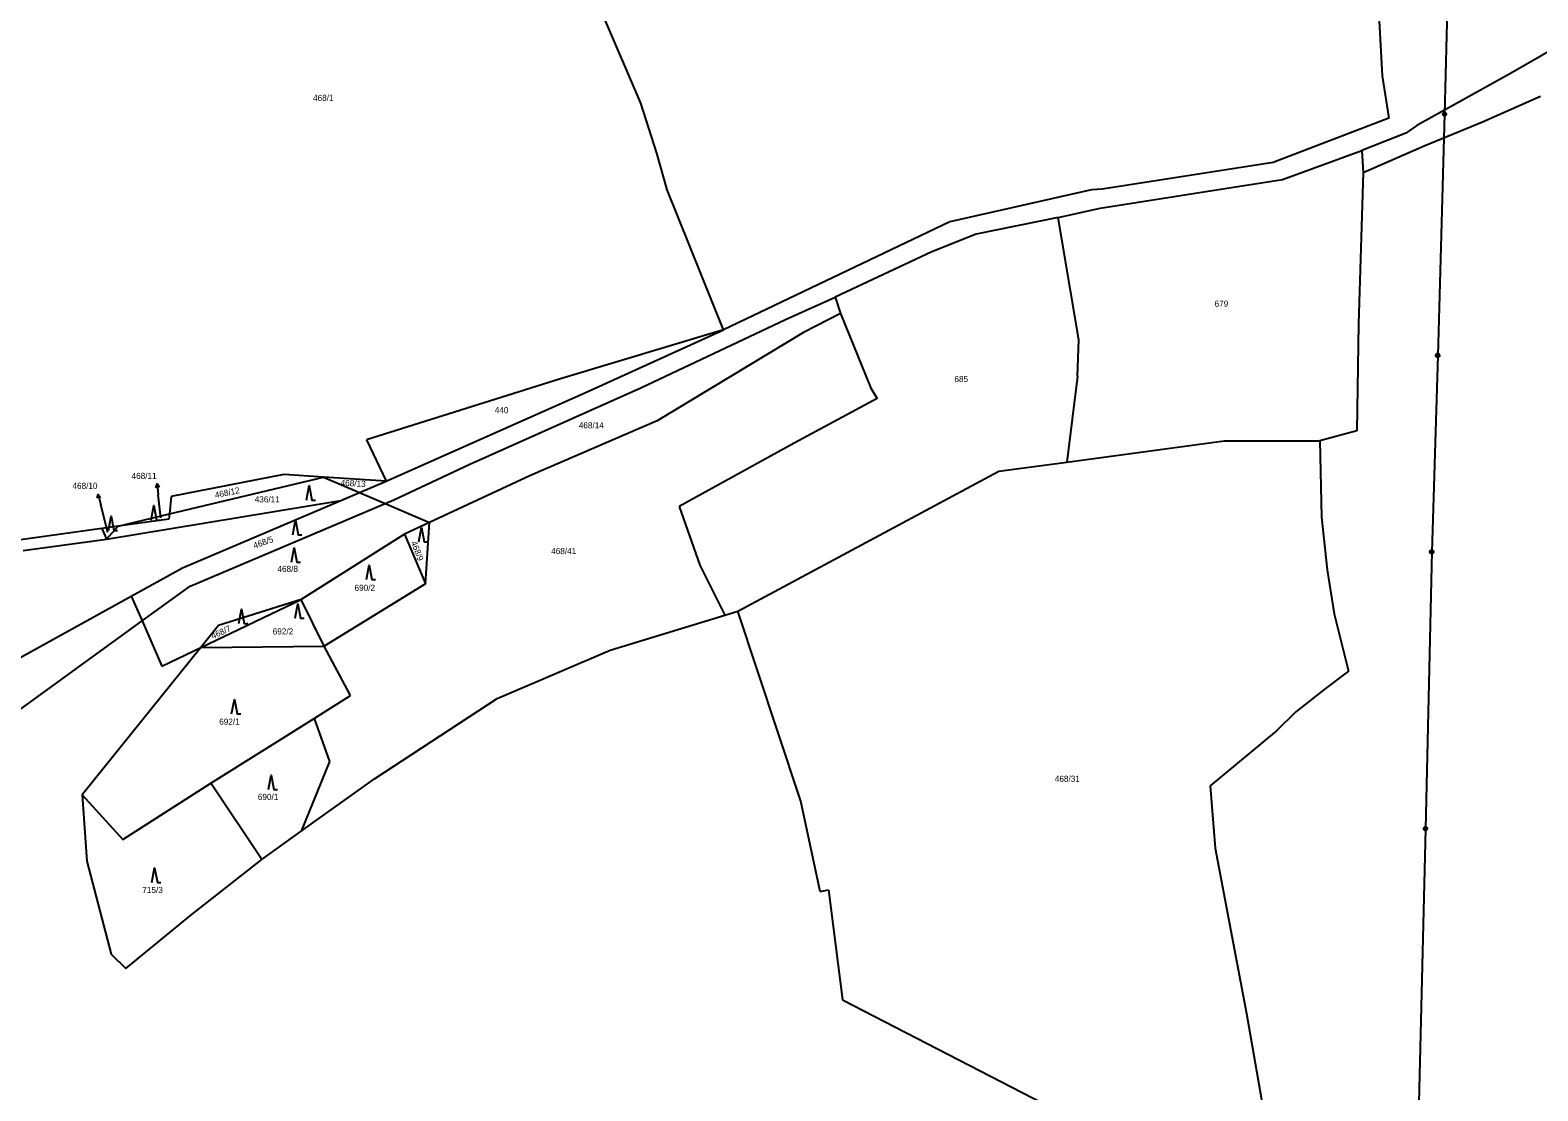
# Model space of a CAD drawing. Extents: x -852001 to -842497, y -1063614 to -1052182.
# Drawn here: x -845490.2 to -845072.7, y -1062182 to -1061888.4 of the extents above; entities that cross this region are included whole.
import ezdxf

# ---------------------------------------------------------------- set-up
doc = ezdxf.new("R2010")
doc.units = 0
for name, color, linetype in [('Default', 7, 'Continuous'), ('KN_HRANICE', 7, 'Continuous'), ('KN_KULTURY', 7, 'Continuous'), ('KN_PARCELY', 7, 'Continuous'), ('KN_VEDENI', 7, 'Continuous')]:
    doc.layers.add(name, color=color, linetype=linetype)

# ---------------------------------------------------------------- blocks, each defined once
blk = doc.blocks.new('308')
at = {"layer": 'Default'}
blk.add_lwpolyline([(-0.75, 0), (0, 4), (0.75, 0), (1.75, 0)], dxfattribs=at)
blk = doc.blocks.new('10292')
at = {"layer": 'Default'}
blk.add_line((0, 3), (0, 0), dxfattribs=at)
blk.add_lwpolyline([(-0.5, 2), (0, 3), (0.5, 2)], dxfattribs=at)
blk = doc.blocks.new('601')
at = {"layer": 'Default'}
blk.add_lwpolyline([(-0.15, 0.48), (0.16, 0.48), (0.41, 0.3), (0.51, 0.01), (0.41, -0.28), (0.16, -0.46), (-0.15, -0.46), (-0.4, -0.28), (-0.5, 0.01), (-0.4, 0.3), (-0.15, 0.48), (-0.12, 0.44), (0.12, 0.44), (0.28, 0.36), (-0.28, 0.36), (-0.36, 0.28), (0.36, 0.28), (0.36, 0.2), (-0.36, 0.2), (-0.4, 0.12), (0.4, 0.12), (0.44, 0.04), (-0.44, 0.04), (-0.44, -0.04), (0.44, -0.04), (0.41, -0.12), (-0.4, -0.12), (-0.39, -0.2), (0.42, -0.2), (0.37, -0.28), (-0.35, -0.28), (-0.27, -0.36), (0.29, -0.36), (0.18, -0.44), (-0.16, -0.44)], dxfattribs=at)

msp = doc.modelspace()

# ---------------------------------------------------------------- linework, layer by layer
at = {"layer": 'KN_HRANICE'}
for p, q in [((-845117.56, -1061869.75), (-845115.87, -1061901.09)), ((-845117.56, -1061869.75), (-845115.87, -1061901.09)), ((-845321.09, -1061908.67), (-845331.76, -1061883.94)), ((-845321.09, -1061908.67), (-845331.76, -1061883.94)), ((-845067.31, -1061892.92), (-845080.32, -1061900.42)), ((-845067.31, -1061892.92), (-845080.32, -1061900.42)), ((-845115.87, -1061901.09), (-845114, -1061912.83)), ((-845115.87, -1061901.09), (-845114, -1061912.83)), ((-845080.32, -1061900.42), (-845094.38, -1061908.29)), ((-845080.32, -1061900.42), (-845094.38, -1061908.29)), ((-845094.38, -1061908.29), (-845106.22, -1061914.77)), ((-845094.38, -1061908.29), (-845106.22, -1061914.77)), ((-845088.09, -1061913.84), (-845071.99, -1061906.71)), ((-845088.09, -1061913.84), (-845071.99, -1061906.71)), ((-845316.7, -1061922.48), (-845321.09, -1061908.67)), ((-845316.7, -1061922.48), (-845321.09, -1061908.67)), ((-845114, -1061912.83), (-845146, -1061925.02)), ((-845114, -1061912.83), (-845146, -1061925.02)), ((-845109.28, -1061916.9), (-845121.49, -1061921.71)), ((-845109.28, -1061916.9), (-845121.49, -1061921.71)), ((-845106.22, -1061914.77), (-845109.28, -1061916.9)), ((-845106.22, -1061914.77), (-845109.28, -1061916.9)), ((-845104.19, -1061920.41), (-845088.09, -1061913.84)), ((-845104.19, -1061920.41), (-845088.09, -1061913.84)), ((-845121.12, -1061927.82), (-845104.19, -1061920.41)), ((-845121.12, -1061927.82), (-845104.19, -1061920.41)), ((-845313.82, -1061932.65), (-845316.7, -1061922.48)), ((-845313.82, -1061932.65), (-845316.7, -1061922.48)), ((-845146, -1061925.02), (-845193.41, -1061932.48)), ((-845146, -1061925.02), (-845193.41, -1061932.48)), ((-845143.47, -1061929.78), (-845121.49, -1061921.71)), ((-845143.47, -1061929.78), (-845121.49, -1061921.71)), ((-845121.49, -1061921.71), (-845121.12, -1061927.82)), ((-845121.49, -1061921.71), (-845121.12, -1061927.82)), ((-845121.12, -1061927.82), (-845122.4, -1061969.73)), ((-845121.12, -1061927.82), (-845122.4, -1061969.73)), ((-845298.2, -1061971.35), (-845313.82, -1061932.65)), ((-845298.2, -1061971.35), (-845313.82, -1061932.65)), ((-845196.29, -1061932.65), (-845235.53, -1061941.44)), ((-845196.29, -1061932.65), (-845235.53, -1061941.44)), ((-845193.41, -1061932.48), (-845196.29, -1061932.65)), ((-845193.41, -1061932.48), (-845196.29, -1061932.65)), ((-845193.91, -1061937.74), (-845164.67, -1061933.11)), ((-845193.91, -1061937.74), (-845164.67, -1061933.11)), ((-845164.67, -1061933.11), (-845143.47, -1061929.78)), ((-845164.67, -1061933.11), (-845143.47, -1061929.78)), ((-845205.52, -1061940.3), (-845193.91, -1061937.74)), ((-845205.52, -1061940.3), (-845193.91, -1061937.74)), ((-845235.53, -1061941.44), (-845298.2, -1061971.35)), ((-845235.53, -1061941.44), (-845298.2, -1061971.35)), ((-845205.52, -1061940.3), (-845228.28, -1061944.89)), ((-845205.52, -1061940.3), (-845228.28, -1061944.89)), ((-845199.81, -1061974.13), (-845205.52, -1061940.3)), ((-845199.81, -1061974.13), (-845205.52, -1061940.3)), ((-845228.28, -1061944.89), (-845240.56, -1061949.77)), ((-845228.28, -1061944.89), (-845240.56, -1061949.77)), ((-845240.56, -1061949.77), (-845267.32, -1061962.35)), ((-845240.56, -1061949.77), (-845267.32, -1061962.35)), ((-845281.07, -1061968.54), (-845267.32, -1061962.35)), ((-845281.07, -1061968.54), (-845267.32, -1061962.35)), ((-845267.32, -1061962.35), (-845265.84, -1061966.86)), ((-845267.32, -1061962.35), (-845265.84, -1061966.86)), ((-845265.84, -1061966.86), (-845276.07, -1061972.09)), ((-845265.84, -1061966.86), (-845276.07, -1061972.09)), ((-845265.84, -1061966.86), (-845257.43, -1061987.52)), ((-845265.84, -1061966.86), (-845257.43, -1061987.52)), ((-845320.93, -1061987.31), (-845281.07, -1061968.54)), ((-845320.93, -1061987.31), (-845281.07, -1061968.54)), ((-845122.4, -1061969.73), (-845122.89, -1061999.33)), ((-845122.4, -1061969.73), (-845122.89, -1061999.33)), ((-845298.2, -1061971.35), (-845343.34, -1061984.91)), ((-845298.2, -1061971.35), (-845343.34, -1061984.91)), ((-845335.79, -1061988.4), (-845298.2, -1061971.35)), ((-845335.79, -1061988.4), (-845298.2, -1061971.35)), ((-845276.07, -1061972.09), (-845316.61, -1061996.53)), ((-845276.07, -1061972.09), (-845316.61, -1061996.53)), ((-845200.21, -1061984.17), (-845199.81, -1061974.13)), ((-845200.21, -1061984.17), (-845199.81, -1061974.13)), ((-845343.34, -1061984.91), (-845397.14, -1062001.82)), ((-845343.34, -1061984.91), (-845397.14, -1062001.82)), ((-845368.48, -1062008.59), (-845320.93, -1061987.31)), ((-845368.48, -1062008.59), (-845320.93, -1061987.31)), ((-845257.43, -1061987.52), (-845255.66, -1061990.37)), ((-845257.43, -1061987.52), (-845255.66, -1061990.37)), ((-845200.21, -1061984.17), (-845203.14, -1062007.97)), ((-845200.21, -1061984.17), (-845203.14, -1062007.97)), ((-845391.63, -1062013.24), (-845335.79, -1061988.4)), ((-845391.63, -1062013.24), (-845335.79, -1061988.4)), ((-845255.66, -1061990.37), (-845278.69, -1062002.78)), ((-845255.66, -1061990.37), (-845278.69, -1062002.78)), ((-845316.61, -1061996.53), (-845351.72, -1062011.72)), ((-845316.61, -1061996.53), (-845351.72, -1062011.72)), ((-845122.89, -1061999.33), (-845133.12, -1062002.1)), ((-845122.89, -1061999.33), (-845133.12, -1062002.1)), ((-845397.14, -1062001.82), (-845391.63, -1062013.24)), ((-845397.14, -1062001.82), (-845391.63, -1062013.24)), ((-845278.69, -1062002.78), (-845310.49, -1062020.31)), ((-845278.69, -1062002.78), (-845310.49, -1062020.31)), ((-845203.14, -1062007.97), (-845159.56, -1062002.1)), ((-845203.14, -1062007.97), (-845159.56, -1062002.1)), ((-845159.56, -1062002.1), (-845133.12, -1062002.1)), ((-845159.56, -1062002.1), (-845133.12, -1062002.1)), ((-845133.12, -1062002.1), (-845132.63, -1062023.19)), ((-845133.12, -1062002.1), (-845132.63, -1062023.19)), ((-845389.56, -1062018.44), (-845368.48, -1062008.59)), ((-845389.56, -1062018.44), (-845368.48, -1062008.59)), ((-845222, -1062010.51), (-845203.14, -1062007.97)), ((-845222, -1062010.51), (-845203.14, -1062007.97)), ((-845451.7, -1062022.34), (-845409.01, -1062012.14)), ((-845451.7, -1062022.34), (-845409.01, -1062012.14)), ((-845420, -1062011.44), (-845451.16, -1062017.46)), ((-845420, -1062011.44), (-845451.16, -1062017.46)), ((-845409.01, -1062012.14), (-845420, -1062011.44)), ((-845409.01, -1062012.14), (-845420, -1062011.44)), ((-845391.63, -1062013.24), (-845409.01, -1062012.14)), ((-845409.01, -1062012.14), (-845399.06, -1062016.4)), ((-845391.63, -1062013.24), (-845409.01, -1062012.14)), ((-845409.01, -1062012.14), (-845399.06, -1062016.4)), ((-845351.72, -1062011.72), (-845379.63, -1062024.73)), ((-845351.72, -1062011.72), (-845379.63, -1062024.73)), ((-845294.32, -1062049.22), (-845222, -1062010.51)), ((-845294.32, -1062049.22), (-845222, -1062010.51)), ((-845404.21, -1062018.6), (-845399.06, -1062016.4)), ((-845404.21, -1062018.6), (-845399.06, -1062016.4)), ((-845399.06, -1062016.4), (-845391.63, -1062013.24)), ((-845399.06, -1062016.4), (-845391.63, -1062013.24)), ((-845399.06, -1062016.4), (-845391.95, -1062019.45)), ((-845399.06, -1062016.4), (-845391.95, -1062019.45)), ((-845469.1, -1062029.34), (-845404.21, -1062018.6)), ((-845469.1, -1062029.34), (-845404.21, -1062018.6)), ((-845451.16, -1062017.46), (-845451.7, -1062022.34)), ((-845451.16, -1062017.46), (-845451.7, -1062022.34)), ((-845448.04, -1062037.26), (-845404.21, -1062018.6)), ((-845448.04, -1062037.26), (-845404.21, -1062018.6)), ((-845445.96, -1062042.32), (-845391.95, -1062019.45)), ((-845445.96, -1062042.32), (-845391.95, -1062019.45)), ((-845391.95, -1062019.45), (-845389.56, -1062018.44)), ((-845391.95, -1062019.45), (-845389.56, -1062018.44)), ((-845391.95, -1062019.45), (-845379.63, -1062024.73)), ((-845391.95, -1062019.45), (-845379.63, -1062024.73)), ((-845310.49, -1062020.31), (-845304.77, -1062036.51)), ((-845310.49, -1062020.31), (-845304.77, -1062036.51)), ((-845465.87, -1062025.72), (-845451.7, -1062022.34)), ((-845465.87, -1062025.72), (-845451.7, -1062022.34)), ((-845451.86, -1062023.75), (-845465.87, -1062025.72)), ((-845451.86, -1062023.75), (-845465.87, -1062025.72)), ((-845451.7, -1062022.34), (-845451.86, -1062023.75)), ((-845451.7, -1062022.34), (-845451.86, -1062023.75)), ((-845379.63, -1062024.73), (-845386.57, -1062027.96)), ((-845379.63, -1062024.73), (-845386.57, -1062027.96)), ((-845380.78, -1062041.68), (-845379.63, -1062024.73)), ((-845380.78, -1062041.68), (-845379.63, -1062024.73)), ((-845132.63, -1062023.19), (-845131.05, -1062037.82)), ((-845132.63, -1062023.19), (-845131.05, -1062037.82)), ((-845470.38, -1062026.35), (-845497.51, -1062030.16)), ((-845470.38, -1062026.35), (-845497.51, -1062030.16)), ((-845492.16, -1062032.41), (-845469.1, -1062029.34)), ((-845492.16, -1062032.41), (-845469.1, -1062029.34)), ((-845465.87, -1062025.72), (-845470.38, -1062026.35)), ((-845465.87, -1062025.72), (-845470.38, -1062026.35)), ((-845470.38, -1062026.35), (-845469.1, -1062029.34)), ((-845470.38, -1062026.35), (-845469.1, -1062029.34)), ((-845469.1, -1062029.34), (-845465.87, -1062025.72)), ((-845469.1, -1062029.34), (-845465.87, -1062025.72)), ((-845386.57, -1062027.96), (-845415.24, -1062046.05)), ((-845386.57, -1062027.96), (-845415.24, -1062046.05)), ((-845386.57, -1062027.96), (-845380.78, -1062041.68)), ((-845386.57, -1062027.96), (-845380.78, -1062041.68)), ((-845462.24, -1062045.1), (-845448.04, -1062037.26)), ((-845462.24, -1062045.1), (-845448.04, -1062037.26)), ((-845304.77, -1062036.51), (-845297.89, -1062050.36)), ((-845304.77, -1062036.51), (-845297.89, -1062050.36)), ((-845131.05, -1062037.82), (-845129.1, -1062050.01)), ((-845131.05, -1062037.82), (-845129.1, -1062050.01)), ((-845380.78, -1062041.68), (-845408.8, -1062058.9)), ((-845380.78, -1062041.68), (-845408.8, -1062058.9)), ((-845506.65, -1062069.62), (-845462.24, -1062045.1)), ((-845506.65, -1062069.62), (-845462.24, -1062045.1)), ((-845462.24, -1062045.1), (-845459.27, -1062051.94)), ((-845462.24, -1062045.1), (-845459.27, -1062051.94)), ((-845459.27, -1062051.94), (-845445.96, -1062042.32)), ((-845459.27, -1062051.94), (-845445.96, -1062042.32)), ((-845442.94, -1062059.27), (-845415.24, -1062046.05)), ((-845442.94, -1062059.27), (-845415.24, -1062046.05)), ((-845415.24, -1062046.05), (-845438.09, -1062053.25)), ((-845415.24, -1062046.05), (-845438.09, -1062053.25)), ((-845408.8, -1062058.9), (-845415.24, -1062046.05)), ((-845408.8, -1062058.9), (-845415.24, -1062046.05)), ((-845329.66, -1062060.07), (-845297.89, -1062050.36)), ((-845329.66, -1062060.07), (-845297.89, -1062050.36)), ((-845297.89, -1062050.36), (-845294.32, -1062049.22)), ((-845297.89, -1062050.36), (-845294.32, -1062049.22)), ((-845283.35, -1062082.09), (-845294.32, -1062049.22)), ((-845283.35, -1062082.09), (-845294.32, -1062049.22)), ((-845129.1, -1062050.01), (-845125.21, -1062065.8)), ((-845129.1, -1062050.01), (-845125.21, -1062065.8)), ((-845499.15, -1062080.77), (-845459.27, -1062051.94)), ((-845499.15, -1062080.77), (-845459.27, -1062051.94)), ((-845459.27, -1062051.94), (-845453.82, -1062064.46)), ((-845459.27, -1062051.94), (-845453.82, -1062064.46)), ((-845438.09, -1062053.25), (-845442.94, -1062059.27)), ((-845438.09, -1062053.25), (-845442.94, -1062059.27)), ((-845442.94, -1062059.27), (-845408.8, -1062058.9)), ((-845442.94, -1062059.27), (-845408.8, -1062058.9)), ((-845401.5, -1062072.6), (-845408.8, -1062058.9)), ((-845401.5, -1062072.6), (-845408.8, -1062058.9)), ((-845442.94, -1062059.27), (-845475.81, -1062100.03)), ((-845442.94, -1062059.27), (-845475.81, -1062100.03)), ((-845453.82, -1062064.46), (-845442.94, -1062059.27)), ((-845453.82, -1062064.46), (-845442.94, -1062059.27)), ((-845360.89, -1062073.42), (-845329.66, -1062060.07)), ((-845360.89, -1062073.42), (-845329.66, -1062060.07)), ((-845125.21, -1062065.8), (-845131.55, -1062070.67)), ((-845125.21, -1062065.8), (-845131.55, -1062070.67)), ((-845131.55, -1062070.67), (-845139.71, -1062077.13)), ((-845131.55, -1062070.67), (-845139.71, -1062077.13)), ((-845411.64, -1062078.95), (-845401.5, -1062072.6)), ((-845411.64, -1062078.95), (-845401.5, -1062072.6)), ((-845394.88, -1062095.61), (-845360.89, -1062073.42)), ((-845394.88, -1062095.61), (-845360.89, -1062073.42)), ((-845440.2, -1062096.85), (-845411.64, -1062078.95)), ((-845440.2, -1062096.85), (-845411.64, -1062078.95)), ((-845411.64, -1062078.95), (-845407.31, -1062090.85)), ((-845411.64, -1062078.95), (-845407.31, -1062090.85)), ((-845139.71, -1062077.13), (-845145.07, -1062082.37)), ((-845139.71, -1062077.13), (-845145.07, -1062082.37)), ((-845276.87, -1062101.86), (-845283.35, -1062082.09)), ((-845276.87, -1062101.86), (-845283.35, -1062082.09)), ((-845145.07, -1062082.37), (-845163.47, -1062097.61)), ((-845145.07, -1062082.37), (-845163.47, -1062097.61)), ((-845407.31, -1062090.85), (-845415.19, -1062110.13)), ((-845407.31, -1062090.85), (-845415.19, -1062110.13)), ((-845415.19, -1062110.13), (-845394.88, -1062095.61)), ((-845415.19, -1062110.13), (-845394.88, -1062095.61)), ((-845475.81, -1062100.03), (-845474.56, -1062118.39)), ((-845475.81, -1062100.03), (-845464.57, -1062112.48)), ((-845475.81, -1062100.03), (-845474.56, -1062118.39)), ((-845475.81, -1062100.03), (-845464.57, -1062112.48)), ((-845464.57, -1062112.48), (-845440.2, -1062096.85)), ((-845464.57, -1062112.48), (-845440.2, -1062096.85)), ((-845426.1, -1062117.93), (-845440.2, -1062096.85)), ((-845426.1, -1062117.93), (-845440.2, -1062096.85)), ((-845163.47, -1062097.61), (-845162.13, -1062114.85)), ((-845163.47, -1062097.61), (-845162.13, -1062114.85)), ((-845271.43, -1062126.82), (-845276.87, -1062101.86)), ((-845271.43, -1062126.82), (-845276.87, -1062101.86)), ((-845426.1, -1062117.93), (-845415.19, -1062110.13)), ((-845426.1, -1062117.93), (-845415.19, -1062110.13)), ((-845162.13, -1062114.85), (-845153.37, -1062160.62)), ((-845162.13, -1062114.85), (-845153.37, -1062160.62)), ((-845474.56, -1062118.39), (-845467.8, -1062144.19)), ((-845474.56, -1062118.39), (-845467.8, -1062144.19)), ((-845445.82, -1062133.47), (-845426.1, -1062117.93)), ((-845445.82, -1062133.47), (-845426.1, -1062117.93)), ((-845271.43, -1062126.82), (-845269.15, -1062126.37)), ((-845271.43, -1062126.82), (-845269.15, -1062126.37)), ((-845269.15, -1062126.37), (-845265.26, -1062156.82)), ((-845269.15, -1062126.37), (-845265.26, -1062156.82)), ((-845463.75, -1062148.16), (-845445.82, -1062133.47)), ((-845463.75, -1062148.16), (-845445.82, -1062133.47)), ((-845467.8, -1062144.19), (-845463.75, -1062148.16)), ((-845467.8, -1062144.19), (-845463.75, -1062148.16)), ((-845265.26, -1062156.82), (-845182.76, -1062199.3)), ((-845265.26, -1062156.82), (-845182.76, -1062199.3)), ((-845153.37, -1062160.62), (-845148.98, -1062185.97)), ((-845153.37, -1062160.62), (-845148.98, -1062185.97))]:
    msp.add_line(p, q, dxfattribs=at)
at = {"layer": 'KN_PARCELY'}
for p, q in [((-845454.02, -1062023.37), (-845454.76, -1062017)), ((-845454.02, -1062023.37), (-845454.76, -1062017)), ((-845468.74, -1062027.51), (-845470.71, -1062019.82)), ((-845468.74, -1062027.51), (-845470.71, -1062019.82))]:
    msp.add_line(p, q, dxfattribs=at)
at = {"layer": 'KN_VEDENI'}
for p, q in [((-845096.73, -1061839.49), (-845098.59, -1061911.71)), ((-845096.73, -1061839.49), (-845098.59, -1061911.71)), ((-845098.59, -1061911.71), (-845100.46, -1061978.44)), ((-845098.59, -1061911.71), (-845100.46, -1061978.44)), ((-845100.46, -1061978.44), (-845102.12, -1062032.83)), ((-845100.46, -1061978.44), (-845102.12, -1062032.83)), ((-845102.12, -1062032.83), (-845103.85, -1062109.44)), ((-845102.12, -1062032.83), (-845103.85, -1062109.44)), ((-845103.85, -1062109.44), (-845105.7, -1062185.21)), ((-845103.85, -1062109.44), (-845105.7, -1062185.21))]:
    msp.add_line(p, q, dxfattribs=at)

# ---------------------------------------------------------------- block references
at = {"layer": 'KN_KULTURY'}
for p in [(-845412.95, -1062018.5), (-845412.95, -1062018.5), (-845456.02, -1062024.02), (-845456.02, -1062024.02), (-845467.79, -1062026.91), (-845467.79, -1062026.91), (-845416.77, -1062028.09), (-845416.77, -1062028.09), (-845381.85, -1062030.07), (-845381.85, -1062030.07), (-845417.17, -1062035.71), (-845417.17, -1062035.71), (-845396.35, -1062040.51), (-845396.35, -1062040.51), (-845431.75, -1062052.67), (-845431.75, -1062052.67), (-845416.09, -1062051.21), (-845416.09, -1062051.21), (-845433.7, -1062077.68), (-845433.7, -1062077.68), (-845423.49, -1062098.61), (-845423.49, -1062098.61), (-845455.77, -1062124.3), (-845455.77, -1062124.3)]:
    msp.add_blockref('308', p, dxfattribs=at)
at = {"layer": 'KN_PARCELY'}
for p, rotation in [((-845470.71, -1062019.82), 14.381241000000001), ((-845470.71, -1062019.82), 14.381241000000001), ((-845454.76, -1062017), 6.646310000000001), ((-845454.76, -1062017), 6.646310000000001)]:
    msp.add_blockref('10292', p, dxfattribs=dict(at, rotation=rotation))
at = {"layer": 'KN_VEDENI'}
for p in [(-845098.59, -1061911.71), (-845098.59, -1061911.71), (-845100.46, -1061978.44), (-845100.46, -1061978.44), (-845102.12, -1062032.83), (-845102.12, -1062032.83), (-845103.85, -1062109.44), (-845103.85, -1062109.44)]:
    msp.add_blockref('601', p, dxfattribs=at)

# ---------------------------------------------------------------- texts
at = {"layer": 'KN_PARCELY'}
for s, height, p in [('468/1', 1.7, (-845411.92, -1061908.02)), ('468/1', 1.7, (-845411.92, -1061908.02)), ('679', 1.7, (-845162.25, -1061964.97)), ('679', 1.7, (-845162.25, -1061964.97)), ('685', 1.7, (-845234.3, -1061985.83)), ('685', 1.7, (-845234.3, -1061985.83)), ('440', 1.7, (-845361.6, -1061994.45)), ('440', 1.7, (-845361.6, -1061994.45)), ('468/14', 1.7, (-845338.33, -1061998.65)), ('468/14', 1.7, (-845338.33, -1061998.65)), ('468/11', 1.7, (-845462.17, -1062012.65)), ('468/11', 1.7, (-845462.17, -1062012.65)), ('468/10', 1.7, (-845478.54, -1062015.39)), ('468/10', 1.7, (-845478.54, -1062015.39)), ('436/11', 1.7, (-845428.07, -1062019.13)), ('436/11', 1.7, (-845428.07, -1062019.13)), ('468/11', 0.1, (-845454.3, -1062023.37)), ('468/11', 0.1, (-845454.3, -1062023.37)), ('468/10', 0.1, (-845469.03, -1062027.51)), ('468/10', 0.1, (-845469.03, -1062027.51)), ('468/41', 1.7, (-845345.97, -1062033.44)), ('468/41', 1.7, (-845345.97, -1062033.44)), ('468/8', 1.7, (-845421.77, -1062038.39)), ('468/8', 1.7, (-845421.77, -1062038.39)), ('690/2', 1.7, (-845400.42, -1062043.62)), ('690/2', 1.7, (-845400.42, -1062043.62)), ('692/2', 1.7, (-845423.08, -1062055.69)), ('692/2', 1.7, (-845423.08, -1062055.69)), ('692/1', 1.7, (-845437.9, -1062080.67)), ('692/1', 1.7, (-845437.9, -1062080.67)), ('468/31', 1.7, (-845206.5, -1062096.48)), ('468/31', 1.7, (-845206.5, -1062096.48)), ('690/1', 1.7, (-845427.2, -1062101.49)), ('690/1', 1.7, (-845427.2, -1062101.49)), ('715/3', 1.7, (-845459.2, -1062127.25)), ('715/3', 1.7, (-845459.2, -1062127.25))]:
    msp.add_text(s, height=height, dxfattribs=at).set_placement(p)
for s, rotation, p in [('468/13', 357.182, (-845404.31, -1062014.53)), ('468/13', 357.182, (-845404.31, -1062014.53)), ('468/12', 11.688, (-845438.91, -1062017.96)), ('468/12', 11.688, (-845438.91, -1062017.96)), ('468/5', 19.996, (-845428.1, -1062031.96)), ('468/5', 19.996, (-845428.1, -1062031.96)), ('468/9', 290.661, (-845384.83, -1062030.19)), ('468/9', 290.661, (-845384.83, -1062030.19)), ('468/7', 24.465, (-845439.65, -1062056.99)), ('468/7', 24.465, (-845439.65, -1062056.99))]:
    msp.add_text(s, height=1.7, rotation=rotation, dxfattribs=at).set_placement(p)

doc.saveas('drawing.dxf')
